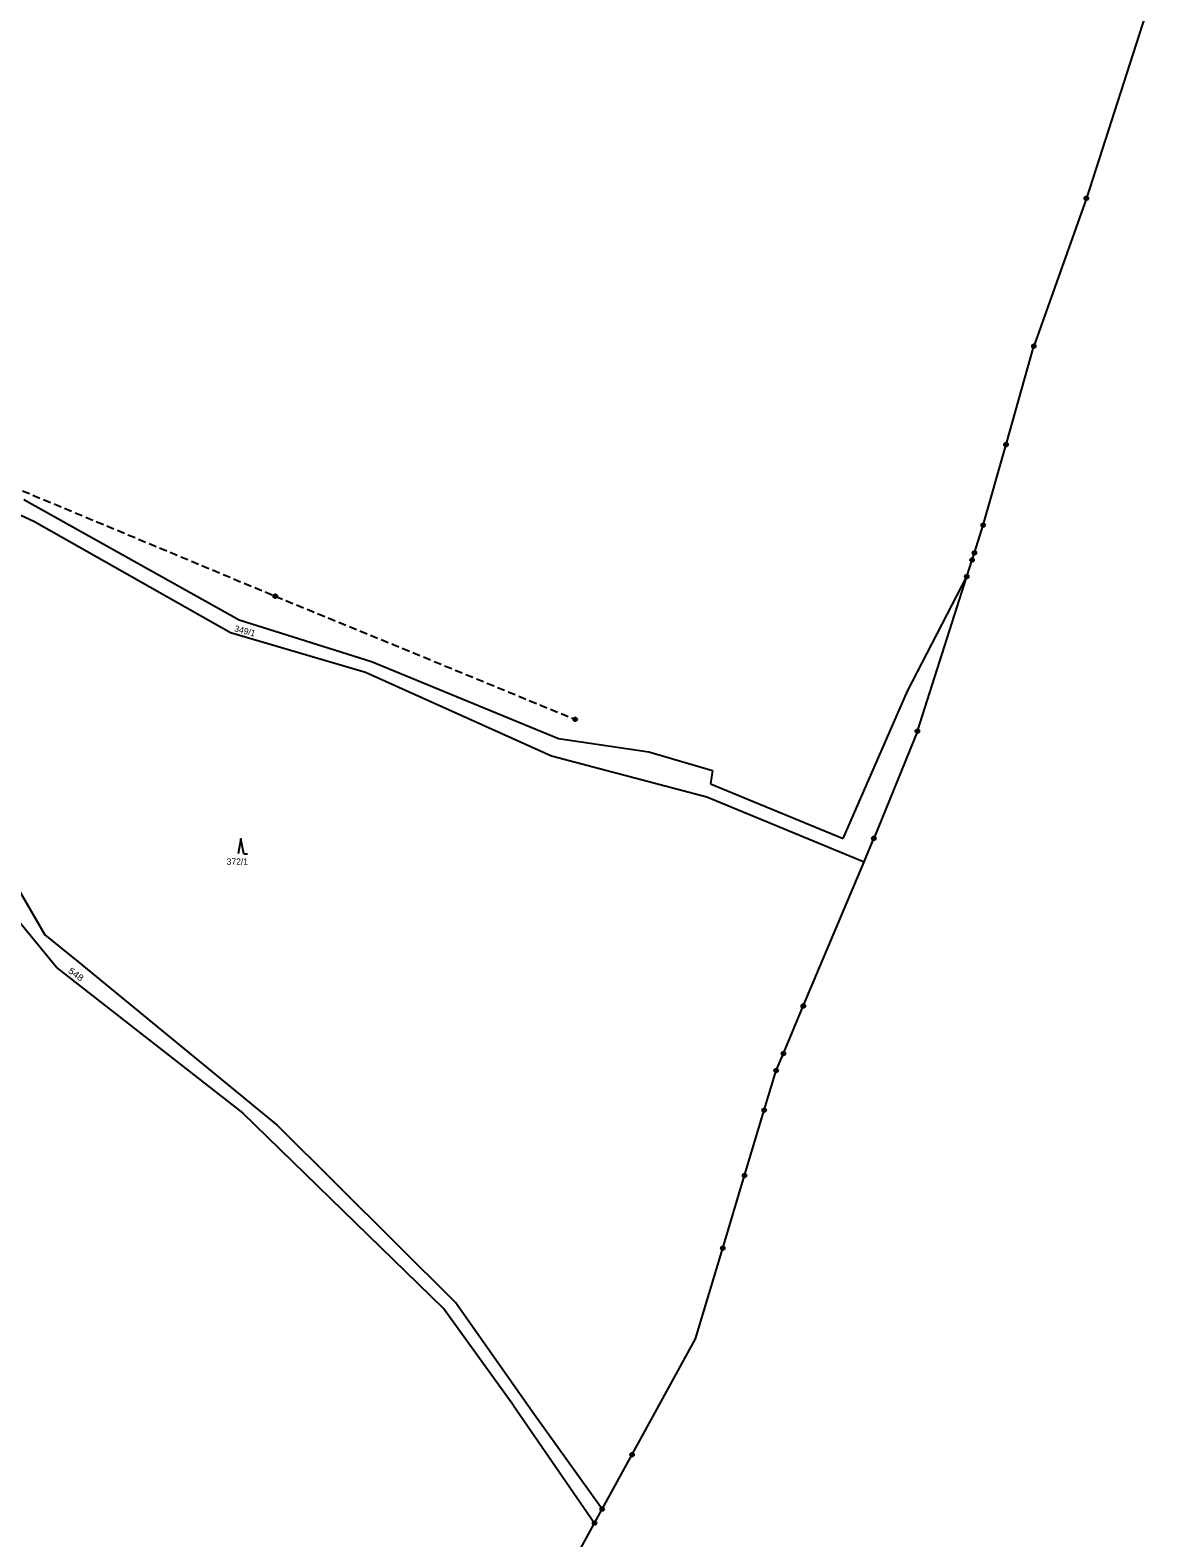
# Model space of a CAD drawing. Extents: x -885985 to -883535, y -1030025 to -1027941.
# Drawn here: x -884022.6 to -883721, y -1029039.3 to -1028636.1 of the extents above; entities that cross this region are included whole.
import ezdxf

# ---------------------------------------------------------------- set-up
doc = ezdxf.new("R2010")
doc.units = 0
doc.header["$LTSCALE"] = 0.68
doc.linetypes.add('MEDIUM_DASHED', pattern=[4.5, 3, -1.5])
for name, color, linetype, lineweight in [('1', 7, 'Continuous', 25), ('3', 7, 'Continuous', 25), ('6', 7, 'Continuous', 25), ('8', 7, 'Continuous', 25)]:
    doc.layers.add(name, color=color, linetype=linetype, lineweight=lineweight)
doc.layers.add('2', color=7, linetype='Continuous')

msp = doc.modelspace()

# ---------------------------------------------------------------- linework, layer by layer
at = {"layer": '1'}
for p, q in [((-883721, -1028621.8), (-883740.13, -1028681.1)), ((-883740.13, -1028681.1), (-883754.15, -1028720.62)), ((-883761.61, -1028746.97), (-883754.15, -1028720.62)), ((-884063.98, -1028747.8), (-884021.67, -1028767.46)), ((-883767.7, -1028768.51), (-883761.61, -1028746.97)), ((-884024.35, -1028761.62), (-883966.75, -1028793.79)), ((-884021.67, -1028767.46), (-883969.04, -1028797.23)), ((-883770.07, -1028775.91), (-883767.7, -1028768.51)), ((-883772.11, -1028782.27), (-883770.68, -1028777.82)), ((-883770.68, -1028777.82), (-883770.07, -1028775.91)), ((-883787.97, -1028812.89), (-883772.11, -1028782.27)), ((-883785.33, -1028823.59), (-883772.11, -1028782.27)), ((-883966.75, -1028793.79), (-883931.38, -1028804.93)), ((-883969.04, -1028797.23), (-883932.97, -1028807.83)), ((-883931.38, -1028804.93), (-883881.34, -1028825.57)), ((-883932.97, -1028807.83), (-883883.2, -1028830.2)), ((-883805.21, -1028852.26), (-883787.97, -1028812.89)), ((-883881.34, -1028825.57), (-883857.13, -1028829.15)), ((-883785.33, -1028823.59), (-883796.97, -1028852.27)), ((-883883.2, -1028830.2), (-883841.61, -1028841.16)), ((-883857.13, -1028829.15), (-883840.11, -1028834.1)), ((-883840.11, -1028834.1), (-883840.64, -1028837.72)), ((-883840.64, -1028837.72), (-883805.21, -1028852.26)), ((-883841.61, -1028841.16), (-883799.6, -1028858.52)), ((-883799.6, -1028858.52), (-883796.97, -1028852.27)), ((-884031.38, -1028856.3), (-884018.74, -1028878.06)), ((-883815.84, -1028897.1), (-883799.6, -1028858.52)), ((-884015.51, -1028886.87), (-884026.38, -1028873.65)), ((-884018.74, -1028878.06), (-884009.93, -1028885.22)), ((-884015.51, -1028886.87), (-883965.87, -1028925.7)), ((-884009.93, -1028885.22), (-883956.47, -1028929.01)), ((-883821.14, -1028909.79), (-883815.84, -1028897.1)), ((-883823.1, -1028914.36), (-883821.14, -1028909.79)), ((-883826.28, -1028924.97), (-883823.1, -1028914.36)), ((-883912.11, -1028978.03), (-883965.87, -1028925.7)), ((-883831.54, -1028942.43), (-883826.28, -1028924.97)), ((-883908.88, -1028976.37), (-883956.47, -1028929.01)), ((-883837.38, -1028961.85), (-883831.54, -1028942.43)), ((-883844.67, -1028986.1), (-883837.38, -1028961.85)), ((-883893.31, -1029003.91), (-883912.11, -1028978.03)), ((-883887.73, -1029006.39), (-883908.88, -1028976.37)), ((-883861.64, -1029017.08), (-883844.67, -1028986.1)), ((-883893.31, -1029003.91), (-883871.66, -1029035.37)), ((-883869.61, -1029031.64), (-883887.73, -1029006.39)), ((-883869.61, -1029031.64), (-883861.64, -1029017.08)), ((-883871.66, -1029035.37), (-883869.61, -1029031.64)), ((-883875.99, -1029043.28), (-883871.66, -1029035.37))]:
    msp.add_line(p, q, dxfattribs=at)
at = {"layer": '3'}
msp.add_line((-883965.5, -1028856.37), (-883964.504, -1028856.37), dxfattribs=at)
msp.add_lwpolyline([(-883965.5, -1028856.37), (-883966.25, -1028852.37), (-883967, -1028856.37)], dxfattribs=at)
at = {"layer": '6', "linetype": 'MEDIUM_DASHED'}
for p, q in [((-884038.84, -1028753.4), (-883957.06, -1028787.49)), ((-883957.06, -1028787.49), (-883876.84, -1028820.43))]:
    msp.add_line(p, q, dxfattribs=at)
at = {"layer": '6'}
for centre, radius in [((-883957.0634, -1028787.4899), 0.5), ((-883957.0634, -1028787.4899), 0.4), ((-883957.0634, -1028787.4899), 0.3), ((-883957.0634, -1028787.4899), 0.2), ((-883957.0634, -1028787.4899), 0.1), ((-883876.8434, -1028820.4299), 0.5), ((-883876.8434, -1028820.4299), 0.4), ((-883876.8434, -1028820.4299), 0.3), ((-883876.8434, -1028820.4299), 0.2), ((-883876.8434, -1028820.4299), 0.1)]:
    msp.add_circle(centre, radius, dxfattribs=at)
at = {"layer": '8'}
for centre, radius in [((-883740.13, -1028681.0999), 0.5), ((-883740.13, -1028681.0999), 0.0303), ((-883754.15, -1028720.6199), 0.5), ((-883754.15, -1028720.6199), 0.0303), ((-883761.61, -1028746.9699), 0.5), ((-883761.61, -1028746.9699), 0.0303), ((-883767.7, -1028768.5099), 0.5), ((-883767.7, -1028768.5099), 0.0303), ((-883770.68, -1028777.8199), 0.5), ((-883770.68, -1028777.8199), 0.0303), ((-883770.07, -1028775.9099), 0.5), ((-883770.07, -1028775.9099), 0.0303), ((-883772.11, -1028782.2699), 0.5), ((-883772.11, -1028782.2699), 0.0303), ((-883785.33, -1028823.5899), 0.5), ((-883785.33, -1028823.5899), 0.0303), ((-883796.97, -1028852.2699), 0.5), ((-883796.97, -1028852.2699), 0.0303), ((-883815.84, -1028897.0999), 0.5), ((-883815.84, -1028897.0999), 0.0303), ((-883821.14, -1028909.7899), 0.5), ((-883821.14, -1028909.7899), 0.0303), ((-883823.1, -1028914.3599), 0.5), ((-883823.1, -1028914.3599), 0.0303), ((-883826.28, -1028924.9699), 0.5), ((-883826.28, -1028924.9699), 0.0303), ((-883831.54, -1028942.4299), 0.5), ((-883831.54, -1028942.4299), 0.0303), ((-883837.38, -1028961.8499), 0.5), ((-883837.38, -1028961.8499), 0.0303), ((-883861.64, -1029017.0799), 0.5), ((-883861.64, -1029017.0799), 0.0303), ((-883869.61, -1029031.6399), 0.5), ((-883869.61, -1029031.6399), 0.0303), ((-883871.66, -1029035.3699), 0.5), ((-883871.66, -1029035.3699), 0.0303)]:
    msp.add_circle(centre, radius, dxfattribs=at)

# ---------------------------------------------------------------- texts
at = {"layer": '2'}
msp.add_text('349/1', height=1.7, rotation=345, dxfattribs=at).set_placement((-883968.149, -1028796.87))
msp.add_text('372/1', height=1.7, dxfattribs=at).set_placement((-883970.07, -1028859.335))
at = {"layer": '2', "width": 1.15}
msp.add_text('548', height=1.7, rotation=324, dxfattribs=at).set_placement((-884012.649, -1028888.033))

doc.saveas('drawing.dxf')
